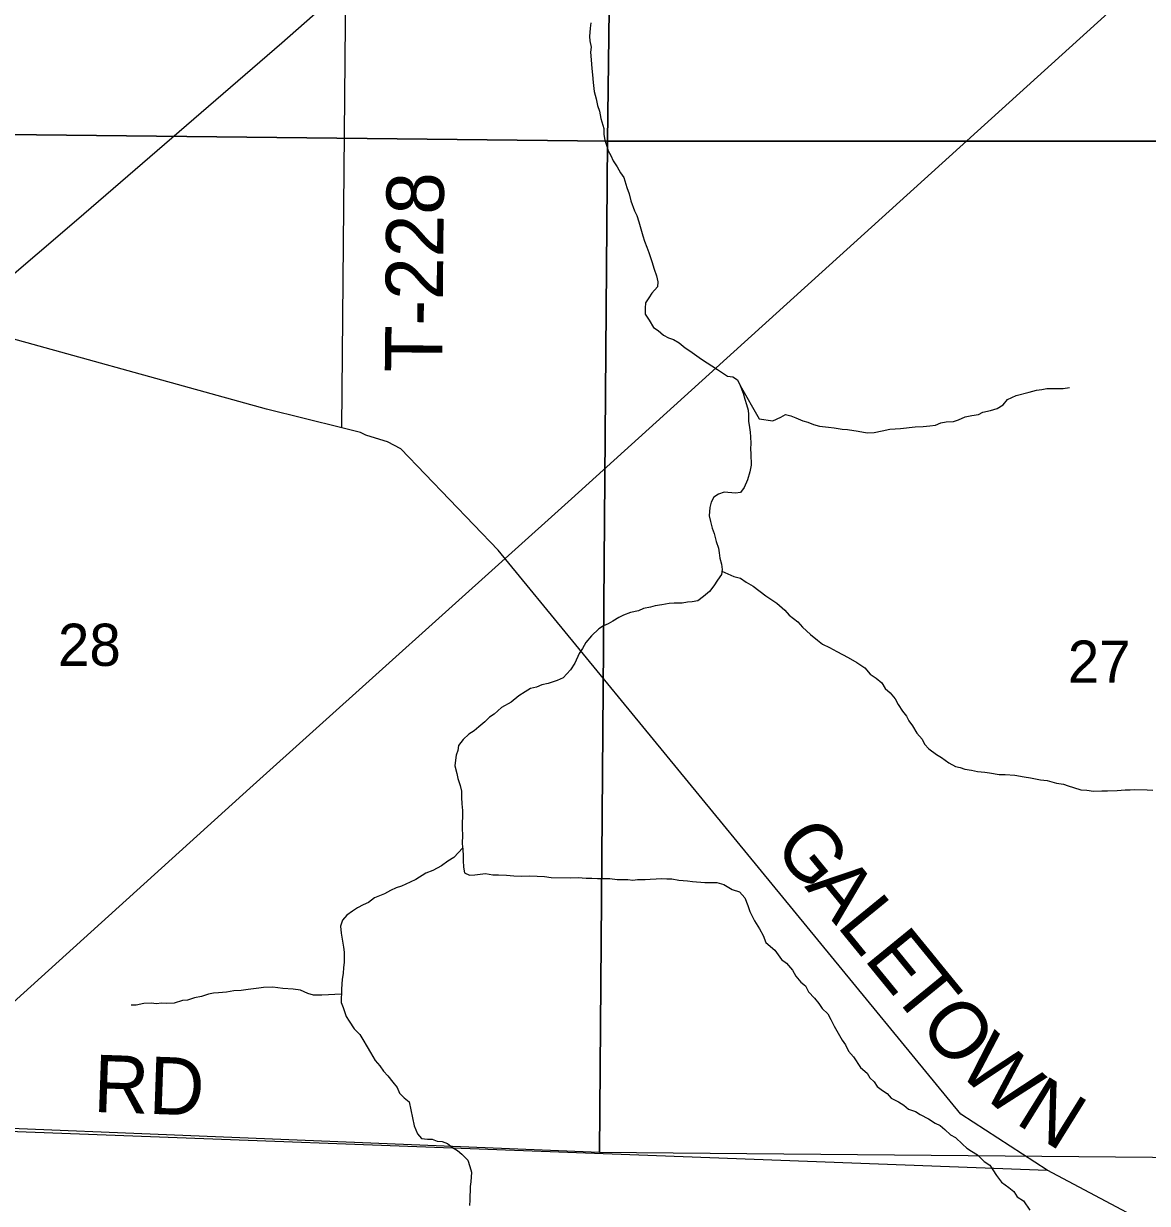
# Model space of a CAD drawing. Extents: x 36.7 to 70.7, y 0 to 22.
# Drawn here: x 43.658 to 44.771, y 14.842 to 16.011 of the extents above; entities that cross this region are included whole.
import ezdxf

# ---------------------------------------------------------------- set-up
doc = ezdxf.new("R2010")
doc.units = 0
for name, color, linetype in [('GM_X_County_Road', 7, 'Continuous'), ('GM_X_Minor_River', 7, 'Continuous'), ('GM_X_Rail_Line', 7, 'Continuous'), ('GM_X_Section', 7, 'Continuous'), ('GM_X_Section_Text', 7, 'Continuous'), ('GM_X_Township_Road', 7, 'Continuous'), ('GM_X_Township_Road_Text', 7, 'Continuous')]:
    doc.layers.add(name, color=color, linetype=linetype)

msp = doc.modelspace()

# ---------------------------------------------------------------- linework, layer by layer
at = {"layer": 'GM_X_County_Road'}
msp.add_lwpolyline([(42.7218, 14.9518), (42.9578, 15.1566), (43.2165, 15.3796), (43.5905, 15.714), (43.7102, 15.8162), (43.9134, 15.9918), (43.977, 16.0478)], dxfattribs=at)
at = {"layer": 'GM_X_Minor_River'}
for points in [[(44.2198, 16.0115), (44.219, 16.0062), (44.2186, 15.9982), (44.2189, 15.9937), (44.22, 15.9876), (44.2195, 15.9827), (44.2202, 15.9751), (44.2208, 15.9663), (44.2215, 15.9602), (44.2222, 15.9526), (44.2232, 15.9435), (44.2251, 15.9363), (44.2265, 15.9298), (44.2283, 15.9241), (44.2298, 15.9169), (44.2327, 15.907), (44.2326, 15.9009), (44.2337, 15.8952), (44.2355, 15.8895), (44.237, 15.8849), (44.2396, 15.8803), (44.2418, 15.875), (44.2459, 15.8689), (44.2493, 15.8631), (44.2526, 15.8585), (44.2555, 15.8486), (44.2577, 15.8422), (44.2596, 15.8353), (44.2632, 15.8254), (44.2655, 15.8208), (44.2673, 15.8143), (44.2688, 15.8098), (44.2713, 15.8006), (44.2731, 15.7953), (44.2754, 15.7892), (44.2772, 15.7839), (44.2801, 15.7751), (44.2827, 15.7675), (44.2849, 15.761), (44.2863, 15.7549), (44.2859, 15.75), (44.2801, 15.7436), (44.2774, 15.7391), (44.274, 15.7342), (44.2735, 15.7289), (44.2738, 15.7228), (44.2776, 15.7171), (44.282, 15.7098), (44.2865, 15.7067), (44.2918, 15.7021), (44.2967, 15.6994), (44.3016, 15.6978), (44.3073, 15.6947), (44.3133, 15.6897), (44.3178, 15.6866), (44.3295, 15.6785), (44.3453, 15.6681), (44.3554, 15.6616), (44.3604, 15.6607), (44.3653, 15.658), (44.3679, 15.6523)], [(44.3679, 15.6523), (44.3708, 15.6447), (44.3723, 15.6386), (44.3741, 15.6333), (44.3756, 15.6279), (44.3759, 15.6234), (44.3762, 15.6169), (44.3769, 15.6108), (44.3776, 15.6059), (44.3779, 15.6013), (44.3782, 15.5949), (44.3781, 15.5896), (44.3785, 15.5846), (44.3787, 15.5732), (44.3775, 15.5668), (44.3751, 15.5589), (44.3716, 15.5513), (44.3682, 15.5464), (44.3632, 15.5457), (44.3519, 15.5466), (44.3462, 15.5447), (44.3416, 15.5417), (44.3392, 15.5365), (44.3377, 15.5315), (44.3372, 15.5232), (44.3383, 15.5175), (44.3401, 15.511), (44.3419, 15.5057), (44.3441, 15.4977), (44.3463, 15.4912), (44.347, 15.4863), (44.3477, 15.4813), (44.3492, 15.4752), (44.3499, 15.4699), (44.3494, 15.465), (44.3452, 15.4593), (44.3417, 15.4537), (44.3375, 15.448), (44.3313, 15.4432), (44.326, 15.439), (44.3203, 15.438), (44.3157, 15.4376), (44.3104, 15.4365), (44.3024, 15.4366), (44.2975, 15.4363), (44.2903, 15.4349), (44.2834, 15.4338), (44.2789, 15.4327), (44.272, 15.4313), (44.2671, 15.429), (44.2591, 15.4272), (44.2522, 15.4246), (44.2477, 15.4224), (44.2415, 15.4187), (44.237, 15.4161), (44.2324, 15.4142), (44.2278, 15.4112), (44.2205, 15.4041), (44.2148, 15.3977), (44.2116, 15.3917), (44.2082, 15.3868), (44.2039, 15.377), (44.1996, 15.3705), (44.1924, 15.3627), (44.1863, 15.3601), (44.1775, 15.3571), (44.1714, 15.3557), (44.1661, 15.3534), (44.16, 15.352), (44.1546, 15.3486), (44.1485, 15.3449), (44.1409, 15.3385), (44.1313, 15.3333), (44.124, 15.3266), (44.1195, 15.3236), (44.1149, 15.3191), (44.1087, 15.3142), (44.1041, 15.3101), (44.0988, 15.3067), (44.0934, 15.3015), (44.0888, 15.2954), (44.088, 15.2905), (44.0864, 15.286), (44.0856, 15.281), (44.0851, 15.2753), (44.087, 15.2677), (44.088, 15.2628), (44.0902, 15.2559), (44.0917, 15.2502), (44.0916, 15.2441), (44.0919, 15.2377), (44.0926, 15.2312), (44.0924, 15.213), (44.0927, 15.2069), (44.0922, 15.1982), (44.0929, 15.1929), (44.0932, 15.186), (44.0932, 15.1815), (44.0935, 15.175), (44.0946, 15.1693), (44.0995, 15.167)], [(44.3679, 15.6523), (44.3865, 15.6191), (44.4001, 15.6174), (44.4081, 15.6208), (44.4127, 15.6234), (44.418, 15.6222), (44.4229, 15.6202), (44.43, 15.6171), (44.435, 15.6159), (44.4406, 15.6136), (44.4463, 15.612), (44.4554, 15.6111), (44.4611, 15.6103), (44.469, 15.6091), (44.4743, 15.6087), (44.4846, 15.607), (44.4936, 15.6054), (44.5005, 15.6057), (44.5085, 15.6072), (44.5161, 15.609), (44.5267, 15.6096), (44.5411, 15.6114), (44.5491, 15.6117), (44.5559, 15.6123), (44.5613, 15.613), (44.5666, 15.6153), (44.5719, 15.6163), (44.5791, 15.6166), (44.5841, 15.6181), (44.5909, 15.6211), (44.5974, 15.6225), (44.6039, 15.6236), (44.6084, 15.6258), (44.616, 15.6276), (44.6225, 15.6295), (44.6286, 15.6332), (44.6329, 15.6385), (44.6412, 15.6422), (44.6542, 15.6455), (44.6614, 15.6477), (44.6667, 15.6484), (44.6717, 15.6494), (44.6827, 15.6493), (44.688, 15.6493), (44.6941, 15.6503)], [(44.3497, 15.4682), (44.3615, 15.463), (44.368, 15.4614), (44.3736, 15.4575), (44.3808, 15.4533), (44.3932, 15.444), (44.4041, 15.4367), (44.412, 15.4298), (44.4165, 15.4248), (44.4251, 15.4182), (44.4296, 15.4129), (44.4375, 15.4056), (44.4446, 15.3998), (44.4495, 15.396), (44.4563, 15.3925), (44.4635, 15.3886), (44.4748, 15.3828), (44.4835, 15.3778), (44.4914, 15.3724), (44.4966, 15.3662), (44.5026, 15.3624), (44.5083, 15.3577), (44.5116, 15.352), (44.5165, 15.3478), (44.5214, 15.3417), (44.5243, 15.3363), (44.5288, 15.3294), (44.5325, 15.3245), (44.5351, 15.3199), (44.5385, 15.3149), (44.543, 15.3076), (44.5482, 15.3019), (44.5504, 15.2969), (44.5549, 15.2923), (44.5625, 15.2866), (44.5674, 15.2838), (44.5745, 15.2785), (44.5813, 15.2746), (44.5858, 15.2738), (44.5904, 15.2722), (44.5972, 15.271), (44.6029, 15.2698), (44.6104, 15.269), (44.615, 15.2685), (44.6244, 15.2669), (44.6305, 15.2668), (44.64, 15.266), (44.6491, 15.2644), (44.6555, 15.2635), (44.6654, 15.2615), (44.6722, 15.2607), (44.6812, 15.2583), (44.6881, 15.2571), (44.693, 15.2555), (44.6983, 15.254), (44.7054, 15.2516), (44.7115, 15.2512), (44.7179, 15.2503), (44.7263, 15.2506), (44.732, 15.2506), (44.7415, 15.2509), (44.7494, 15.2515), (44.7544, 15.2515), (44.7589, 15.2518), (44.7711, 15.2517), (44.7768, 15.2512)], [(44.0928, 15.1941), (44.0841, 15.1846), (44.078, 15.1809), (44.0719, 15.1764), (44.0631, 15.1716), (44.0562, 15.169), (44.0463, 15.1626), (44.0406, 15.16), (44.0322, 15.156), (44.0269, 15.1545), (44.0212, 15.1519), (44.0154, 15.1485), (44.0055, 15.1445), (43.9994, 15.14), (43.9941, 15.1378), (43.9887, 15.1348), (43.9837, 15.1314), (43.978, 15.1273), (43.9738, 15.1224), (43.9718, 15.1164), (43.9725, 15.1095), (43.9746, 15.0958), (43.9753, 15.0909), (43.9752, 15.0806), (43.9748, 15.0757), (43.9743, 15.0696), (43.9735, 15.064), (43.9731, 15.059), (43.9726, 15.0541), (43.9725, 15.0408), (43.9743, 15.0359), (43.9773, 15.0271), (43.9802, 15.0225), (43.9851, 15.0149), (43.9907, 15.0091), (43.9937, 15.0041), (43.9981, 14.9969), (44.0015, 14.9915), (44.006, 14.9835), (44.0108, 14.9781), (44.0142, 14.9728), (44.0187, 14.9682), (44.0235, 14.9621), (44.0277, 14.9567), (44.0302, 14.951), (44.0347, 14.9464), (44.0396, 14.9425), (44.0447, 14.9186), (44.048, 14.9109), (44.0521, 14.906), (44.0578, 14.9055), (44.0624, 14.9055), (44.0676, 14.9035), (44.0726, 14.9031), (44.0779, 14.9011), (44.0827, 14.8973), (44.0876, 14.8942), (44.0921, 14.8907), (44.0978, 14.8846), (44.1, 14.8785), (44.1014, 14.8728), (44.1009, 14.8633), (44.1001, 14.8584), (44.1, 14.8451), (44.0995, 14.8398)], [(44.0995, 15.167), (44.1048, 15.1673), (44.1154, 15.1687), (44.1226, 15.1675), (44.1283, 15.1675), (44.1363, 15.167), (44.1435, 15.1665), (44.151, 15.1661), (44.1594, 15.1664), (44.1666, 15.1659), (44.1738, 15.1658), (44.1806, 15.1646), (44.1992, 15.1644), (44.2072, 15.1647), (44.2151, 15.1642), (44.2208, 15.1642), (44.2265, 15.1637), (44.2386, 15.1636), (44.2458, 15.1628), (44.2565, 15.1627), (44.2614, 15.1622), (44.2659, 15.1626), (44.2735, 15.1629), (44.2785, 15.1632), (44.2845, 15.1635), (44.2898, 15.1638), (44.2952, 15.1634), (44.3001, 15.1633), (44.3069, 15.1621), (44.3156, 15.1613), (44.3205, 15.1608), (44.3327, 15.1599), (44.3448, 15.1598), (44.3516, 15.1578), (44.3599, 15.1528), (44.3671, 15.1505), (44.3723, 15.1447), (44.3753, 15.1371), (44.3775, 15.131), (44.3819, 15.1218), (44.3868, 15.1138), (44.3905, 15.1073), (44.3931, 15.1005), (44.4021, 15.0928), (44.4088, 15.0836), (44.4137, 15.0797), (44.4197, 15.0728), (44.423, 15.0671), (44.4279, 15.061), (44.4324, 15.0575), (44.4354, 15.0514), (44.4414, 15.0453), (44.4459, 15.0399), (44.4492, 15.0349), (44.4548, 15.0296), (44.4578, 15.0242), (44.4611, 15.0174), (44.4649, 15.0105), (44.469, 15.0036), (44.4723, 14.999), (44.4753, 14.9925), (44.4802, 14.9872), (44.4869, 14.9765), (44.4936, 14.9707), (44.4962, 14.9661), (44.5007, 14.9623), (44.5037, 14.9577), (44.509, 14.9538), (44.5135, 14.9507), (44.5176, 14.9461), (44.5248, 14.9423), (44.5301, 14.9392), (44.5346, 14.9353), (44.5414, 14.933), (44.5463, 14.9299), (44.5546, 14.9256), (44.561, 14.9214), (44.5659, 14.919), (44.5707, 14.9152), (44.5764, 14.9098), (44.5813, 14.9071), (44.588, 14.9006), (44.5925, 14.8967), (44.5971, 14.8937), (44.6031, 14.8898), (44.6095, 14.8833), (44.6151, 14.8798), (44.6218, 14.8695), (44.6267, 14.863), (44.6342, 14.8576), (44.6391, 14.8537), (44.6424, 14.8484), (44.6485, 14.8445), (44.6548, 14.835)], [(43.9726, 15.0492), (43.9532, 15.0482), (43.9449, 15.0483), (43.9392, 15.0499), (43.932, 15.053), (43.9248, 15.0542), (43.9146, 15.0547), (43.9048, 15.056), (43.8953, 15.0557), (43.8907, 15.055), (43.8801, 15.0536), (43.8732, 15.0529), (43.866, 15.0526), (43.8588, 15.0511), (43.8508, 15.0505), (43.8459, 15.0501), (43.8409, 15.0491), (43.8341, 15.0469), (43.8269, 15.0454), (43.82, 15.0432), (43.8151, 15.0429), (43.8067, 15.0403), (43.7991, 15.04), (43.7946, 15.0401), (43.7889, 15.0397), (43.7843, 15.0402), (43.7767, 15.0399), (43.7691, 15.0384), (43.7642, 15.0381)]]:
    msp.add_lwpolyline(points, dxfattribs=at)
at = {"layer": 'GM_X_Rail_Line'}
msp.add_lwpolyline([(42.5932, 14.0969), (42.6018, 14.1045), (42.9057, 14.3723), (43.2092, 14.6439), (43.5174, 14.9236), (43.8818, 15.2533), (44.2007, 15.5398), (44.9423, 16.2118), (45.4899, 16.7019), (45.5934, 16.801)], dxfattribs=at)
at = {"layer": 'GM_X_Section'}
for points in [[(44.2493, 16.9097), (44.2362, 15.8944), (43.2232, 15.9056), (43.2397, 16.908)], [(45.2325, 16.9015), (45.2216, 15.8945), (44.2362, 15.8944), (44.2493, 16.9097)], [(44.2362, 15.8944), (44.2284, 14.8924), (43.2077, 14.934), (43.2232, 15.9056)], [(45.2216, 15.8945), (45.2149, 14.8834), (44.2284, 14.8924), (44.2362, 15.8944)]]:
    msp.add_lwpolyline(points, close=True, dxfattribs=at)
at = {"layer": 'GM_X_Township_Road'}
for points in [[(43.973, 15.6102), (43.977, 16.0478), (43.9799, 16.3965)], [(44.2818, 15.3016), (44.1278, 15.4892), (44.0315, 15.5895), (44.0183, 15.5966), (44.0021, 15.6014), (43.9968, 15.603), (43.9915, 15.6057), (43.973, 15.6102), (43.8985, 15.6289), (43.5905, 15.714), (43.5074, 15.7438), (43.4741, 15.7516), (43.2738, 15.762), (43.1602, 15.8481), (43.0617, 15.9325), (43.0175, 16.0153), (42.9702, 16.0985), (42.9678, 16.1373), (42.9675, 16.211)], [(45.0999, 14.6015), (45.0182, 14.6667), (44.8966, 14.7532), (44.8251, 14.7935), (44.6722, 14.8746), (44.5866, 14.9303), (44.2818, 15.3016)], [(42.7218, 14.9518), (43.2111, 14.9295), (44.6722, 14.8746)]]:
    msp.add_lwpolyline(points, dxfattribs=at)

# ---------------------------------------------------------------- texts
at = {"layer": 'GM_X_Section_Text'}
for s, p in [('28', (43.6917, 15.3744)), ('27', (44.6925, 15.3577))]:
    msp.add_text(s, height=0.04186, rotation=0, dxfattribs=at).set_placement(p)
at = {"layer": 'GM_X_Township_Road_Text'}
for s, height, rotation, p in [('T-228', 0.05682, 89.4386, (44.0724, 15.665)), ('G', 0.0568, 309.2384, (44.3994, 15.1943)), ('A', 0.0568, 309.2373, (44.4311, 15.1556)), ('L', 0.0568, 309.2383, (44.4627, 15.1169)), ('E', 0.0568, 309.2388, (44.4896, 15.084)), ('T', 0.0568, 309.2388, (44.5165, 15.051)), ('O', 0.0568, 309.3969, (44.5435, 15.018)), ('W', 0.0568, 317.7868, (44.5815, 14.9728)), ('RD', 0.05682, 358.0252, (43.7262, 14.9325)), ('N', 0.0568, 328.1353, (44.6392, 14.9218))]:
    msp.add_text(s, height=height, rotation=rotation, dxfattribs=at).set_placement(p)

doc.saveas('drawing.dxf')
